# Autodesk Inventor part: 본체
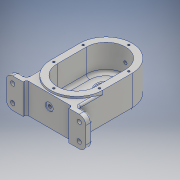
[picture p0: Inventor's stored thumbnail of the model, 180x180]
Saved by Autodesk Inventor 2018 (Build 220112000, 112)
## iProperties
Created: 2021-05
Part Number: 본체
Material: 알루미늄 6061
Document SubType Name: Modeling
Designer: Admin
Density: 2.7 g/cm^3
Appearance: 알루미늄 - 평지
Mass: 756.755 g
Surface Area: 581.829 cm^2
Volume: 280.28 cm^3
Author: Admin
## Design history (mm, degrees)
sketch "스케치1"
  geometry: L1 (0, -22.5)-(0, 22.5); L2 (-40, -22.5)-(-40, 22.5); L3 (40, 22.5)-(40, -22.5); A1 r 40 centre (0, -22.5) between (-40, -22.5) and (40, -22.5); A2 r 40 centre (0, 22.5) between (40, 22.5) and (-40, 22.5); 2 further points
  constraints: 8 end point, 4 point on circle, 4 tangent, 2 centre point, 1 coincident, 1 midpoint, 1 parallel, 1 vertical
  dimensions: "d0" = 80 distance between parallel lines of L3 L2; "d1" = 45 distance of L1.start L1.end
extrude "돌출1" new body sketch "스케치1" stored distance "d2" = 49; taper "d3" = 0 deg
sketch "스케치3"
  geometry: L1 (-69.5, 21.5)-(-59.5, 21.5); L2 (-59.5, 21.5)-(-59.5, -24.5); L3 (-59.5, -24.5)-(-69.5, -24.5); L4 (-69.5, -24.5)-(-69.5, 21.5); L5 (-62.5, -24.5)-(-22.5, -24.5) reference; L6 (22.5, 24.5)-(22.5, -24.5) reference; L7 (22.5, 24.5)-(22.5, 24.5) reference; L8 (22.5, 24.5)-(22.5, -24.5) reference; L9 (22.5, -24.5)-(22.5, -24.5) reference; L10 (62.5, -24.5)-(62.5, 24.5) reference; 1 further point
  constraints: 8 end point, 2 parallel, 1 collinear, 1 horizontal, 1 perpendicular
  dimensions: "d8" = 46 distance of L3.end L1.start; "d13" = 132 distance between parallel lines of L10 L4; "d14" = 10 distance between parallel lines of L4 L2
extrude "돌출3" join sketch "스케치3" stored distance "d11" = 122; taper "d12" = 0 deg
sketch "스케치4"
  geometry: L1 (-55.199, 46)-(24.801, 46); L2 (24.801, 46)-(24.801, 0); L3 (24.801, 0)-(-55.199, 0); L4 (-55.199, 0)-(-55.199, 46); L5 (-100.599, 21.5)-(70.201, 21.5) reference; L6 (-15.199, 55.8)-(-15.199, -12.8) reference; L7 (45.801, 46)-(-76.199, 46) reference; 2 further points
  constraints: 8 end point, 2 midpoint, 2 parallel, 1 horizontal, 1 perpendicular, 1 other
  dimensions: "d15" = 46 distance of L1.end L2.end; "d16" = 80 distance of L1.start L1.end
extrude "돌출4" join sketch "스케치4" distance "d17" = 40; taper "d18" = 0 deg
sketch "스케치5"
  geometry: L1 (-40, 22.5)-(-40, -22.5) reference; L2 (40, -22.5)-(40, 22.5) reference; L3 (0, 22.5)-(0, -22.5); L4 (-30, 22.5)-(-30, -22.5); L5 (30, -22.5)-(30, 22.5); A1 r 40 centre (0, -22.5) between (-40, -22.5) and (40, -22.5) reference; A2 r 40 centre (0, 22.5) between (40, 22.5) and (-40, 22.5) reference; A3 r 30 centre (0, 22.5) between (30, 22.5) and (-30, 22.5); A4 r 30 centre (0, -22.5) between (-30, -22.5) and (30, -22.5); 2 further points
  constraints: 8 end point, 4 point on circle, 4 tangent, 2 centre point, 1 midpoint, 1 parallel, 1 vertical
  dimensions: "d19" = 30 radius of A3
extrude "돌출5" cut sketch "스케치5" distance "d20" = 41; taper "d21" = 0 deg
sketch "스케치6"
  geometry: L1 (0, 22.5)-(0, -22.5); L2 (-26, 22.5)-(-26, -22.5); L3 (26, -22.5)-(26, 22.5); A1 r 26 centre (0, 22.5) between (26, 22.5) and (-26, 22.5); A2 r 26 centre (0, -22.5) between (-26, -22.5) and (26, -22.5); 2 further points
  constraints: 8 end point, 4 point on circle, 4 tangent, 2 centre point, 1 coincident, 1 midpoint, 1 parallel, 1 vertical
  dimensions: "d22" = 52 distance between parallel lines of L3 L2; "d23" = 45 distance of L1.start L1.end
extrude "돌출6" join sketch "스케치6" distance "d24" = 8; taper "d25" = 0 deg
sketch "스케치7"
  geometry: L1 (0, -22.5)-(0, 22.5); L2 (-26, -22.5)-(-26, -7.5); L3 (26, -7.5)-(26, -22.5); L4 (26, 22.5)-(26, -22.5) reference; L5 (26, 22.5)-(-26, 22.5); L6 (-26, -7.5)-(26, -7.5); A1 r 26 centre (0, -22.5) between (-26, -22.5) and (26, -22.5); A2 r 26 centre (0, 22.5) between (26, 22.5) and (-26, 22.5); 2 further points
  constraints: 12 end point, 4 point on circle, 4 tangent, 2 centre point, 2 perpendicular, 1 coincident, 1 midpoint, 1 parallel, 1 point on line, 1 vertical
  dimensions: "d29" = 30 distance between parallel lines of L6 L5
extrude "돌출7" join sketch "스케치7" distance "d30" = 3; taper "d31" = 0 deg
sketch "스케치8"
  geometry: L1 (22.5, 59.59)-(22.5, -61.115); L2 (22.5, 24.5)-(22.5, -16.5) reference; L3 (22.5, -16.5)-(36.5, -16.5); L4 (22.5, -16.5)-(52.5, -16.5) reference; L5 (36.5, -16.5)-(36.5, -24.2); L6 (36.2, -24.5)-(33.5, -24.5); L7 (33.5, -24.5)-(33.5, -28.5); L8 (33.5, -28.5)-(36.5, -28.5); L9 (36.5, -28.5)-(36.5, -32.5); L10 (22.5, -32.5)-(48.5, -32.5) reference; L11 (36.5, -32.5)-(22.5, -32.5); L12 (22.5, -32.5)-(22.5, -16.5); A1 r 0.3 centre (36.2, -24.2) between (36.2, -24.5) and (36.5, -24.2); 3 further points
  constraints: 18 end point, 7 point on line, 3 perpendicular, 2 point on circle, 2 tangent, 2 vertical, 1 centre point, 1 collinear, 1 horizontal, 1 midpoint
  dimensions: "d32" = 8 distance of L3.end point (36.5, -24.5); "d33" = 4 distance of L8.end L9.end; "d34" = 22 diameter of L7 L1; "d35" = 28 diameter of L9 L1; "d36" = 0.3 radius of A1
revolve "회전1" sketch "스케치8" stored, may be unused: angle "d37" = 90 deg
sketch "스케치9"
  geometry: L1 (-22.5, 24.5)-(-22.5, -16.5) reference; L2 (-22.5, 33.135)-(-22.5, -85.217); L3 (-8.5, -16.5)-(-8.5, -24.2); L4 (-8.8, -24.5)-(-12.5, -24.5); L5 (-12.5, -24.5)-(-12.5, -25.5); L6 (-15.5, -28.5)-(-22.5, -28.5); L7 (-22.5, -28.5)-(-22.5, -16.5); L8 (-22.5, -16.5)-(-8.5, -16.5); L9 (-22.5, -16.5)-(22.5, -16.5) reference; A1 r 3 centre (-15.5, -25.5) between (-15.5, -28.5) and (-12.5, -25.5); A2 r 0.3 centre (-8.8, -24.2) between (-8.8, -24.5) and (-8.5, -24.2); 4 further points
  constraints: 14 end point, 6 point on line, 4 point on circle, 4 tangent, 3 perpendicular, 2 centre point, 2 collinear, 2 vertical, 1 midpoint
  dimensions: "d38" = 8 distance of L3.start point (-8.5, -24.5); "d39" = 28 diameter of L3 L2; "d40" = 20 diameter of L5 L2; "d41" = 4 distance of L4.end point (-12.5, -28.5); "d42" = 3 radius of A1; "d43" = 0.3 radius of A2
revolve "회전2" sketch "스케치9" stored, may be unused: angle "d44" = 90 deg
fillet "모깎기1" dims "d45" = 10
sketch "스케치10"
  geometry: L1 (11, 46)-(-91, 46) reference; L2 (21, 10)-(21, 36) reference; L3 (-91, 0)-(11, 0) reference; L4 (-101, 36)-(-101, 10) reference; A1 r 10 centre (-91, 36) between (-91, 46) and (-101, 36) reference; A2 r 10 centre (11, 36) between (21, 36) and (11, 46) reference; A3 r 10 centre (11, 10) between (11, 0) and (21, 10) reference; A4 r 10 centre (-91, 10) between (-101, 10) and (-91, 0) reference; 5 further points
  constraints: 4 coincident
hole "구멍1" sketch "스케치10" at (-91, 10), (-91, 36), (11, 36), (11, 10) diameter "d46" = 6.6; stored, may be unused: countersink angle "d50" = 90 deg, drill point angle "d52" = 118 deg; dims "d47" = 6, "d48" = 11, "d49" = 2, "d51" = 11
node "작업 평면1"
sketch "스케치11"
  geometry: L1 (91, 49)-(11, 49) reference; L2 (51, -23)-(51, 61) reference; C1 r 6 at (51, 28); 1 further point
  constraints: 1 centre point, 1 point on line
  dimensions: "d54" = 12 diameter of C1; "d55" = 21 distance from line of L1 C1.centre
extrude "돌출8" join sketch "스케치11" stored distance "d56" = 3; taper "d57" = 0 deg
sketch "스케치12"
  geometry: L1 (51, -47)-(-51, -47) reference; L2 (-35, -47)-(35, -47); L3 (35, -47)-(35, -42); L4 (35, -42)-(-35, -42); L5 (-35, -42)-(-35, -47); L6 (0, -74)-(0, 115) reference; 1 further point
  constraints: 8 end point, 2 parallel, 1 horizontal, 1 perpendicular, 1 point on line, 1 other
  dimensions: "d58" = 70 distance of L3.end L4.end; "d59" = 5 distance of L2.end L3.end
extrude "돌출9" cut sketch "스케치12" extent not by distance; stored distance "d60" = 3; taper "d61" = 0 deg
sketch "스케치13"
  geometry: C1 r 6 at (0, 0) reference; 2 further points
  constraints: 1 coincident
hole "구멍2" sketch "스케치13" at (0, 0) diameter "d62" = 4.917; stored, may be unused: countersink angle "d66" = 90 deg, drill point angle "d68" = 118 deg; dims "d63" = 135, "d64" = 11, "d65" = 2, "d67" = 17.1
sketch "스케치14"
  geometry: C1 r 6 at (35, -18) reference; C2 r 6 at (35, -18); 1 further point
  constraints: 1 centre point, 1 coincident
  dimensions: "d69" = 12 diameter of C2
extrude "돌출10" cut sketch "스케치14" distance "d70" = 1; taper "d71" = 0 deg
sketch "스케치15"
  geometry: L1 (0, -22.5)-(0, 22.5); L2 (35, -22.5)-(35, 22.5); L3 (-35, 22.5)-(-35, -22.5); C1 r 11 at (0, 22.5) reference; C2 r 10 at (0, -22.5) reference; A1 r 35 centre (0, -22.5) between (-35, -22.5) and (35, -22.5); A2 r 35 centre (0, 22.5) between (35, 22.5) and (-35, 22.5); 8 further points
  constraints: 8 end point, 6 point on circle, 4 coincident, 4 tangent, 2 centre point, 1 midpoint, 1 parallel, 1 vertical
  dimensions: "d72" = 70 diameter of A2
hole "구멍3" sketch "스케치15" at (0, 57.5), (35, 22.5), (-35, 22.5), (-35, -22.5), (35, -22.5), (0, -57.5) diameter "d73" = 3.242; stored, may be unused: countersink angle "d77" = 90 deg, drill point angle "d79" = 118 deg; dims "d74" = 8, "d75" = 11, "d76" = 2, "d78" = 10
sketch "스케치16" dims "d80" = 40
  geometry: L1 (0, -96.5)-(0, 92.5) reference; C1 r 14 at (0, 22.5) reference; 5 further points
  constraints: 1 coincident, 1 point on line, 1 vertical alignment, 6 other
  dimensions: "d83" = 360 deg dimension on C1.centre point (0, 42.5) (derived)
hole "구멍4" sketch "스케치16" at (0, 42.5), (-17.321, 12.5), (17.321, 12.5) diameter "d85" = 3.242; stored, may be unused: countersink angle "d89" = 90 deg, drill point angle "d91" = 118 deg; dims "d86" = 8, "d87" = 11, "d88" = 2, "d90" = 10
fillet "모깎기2" dims "d92" = 5
fillet "모깎기3" dims "d93" = 3
fillet "모깎기4" dims "d94" = 3
chamfer "모따기1" distance "d95" = 1; stored, may be unused: second distance "d96" = 2, angle "d97" = 45 deg
sketch "스케치17"
  geometry: L1 (0, -96.506)-(0, 92.534) reference; L2 (-51, -69.5)-(-61, -69.5) reference; 2 further points
  constraints: 1 point on line, 1 other
  dimensions: "d98" = 12 distance from line of L2 point (0, -57.5)
feature "엠보싱1" sketch "스케치17" dims "d0" = 80, "d1" = 45, "d43" = 0.3, "d83" = 360 deg (derived), "d99" = 0.5, "d100" = 0
node "솔리드1"
node "투영된 루프1"
node "투영된 루프2"
node "투영된 루프3"
other parameters: "d53" = -135
